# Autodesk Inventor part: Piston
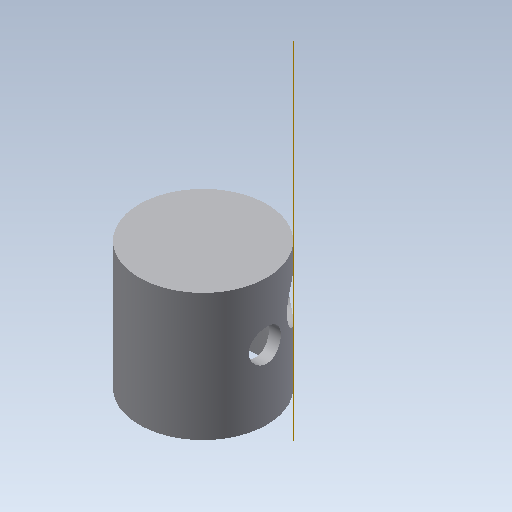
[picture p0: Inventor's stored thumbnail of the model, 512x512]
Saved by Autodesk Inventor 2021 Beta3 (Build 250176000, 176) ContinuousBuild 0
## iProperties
Created: 2012-08
Part Number: Piston
Material: Aluminum 6061
Document SubType Name: Modeling
Designer: John
Mass: 1.96844 g
Surface Area: 13.1985 cm^2
Volume: 0.72636 cm^3
Density: 2.71 g/cm^3
Appearance: Aluminum - Flat
Author: John
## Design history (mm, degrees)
sketch "Sketch1"
  geometry: C1 r 6.921 at (0, 0); 1 further point
  constraints: 1 centre point, 1 coincident
  dimensions: "d0" = 13.843 diameter of C1
extrude "Extrusion1" new body sketch "Sketch1" distance "d1" = 13.843; taper "d2" = 0 deg
hole "Hole2" diameter "d14" = 12.192; stored, may be unused: countersink angle "d18" = 82 deg, drill point angle "d20" = 0 deg; dims "d12" = 25.4, "d13" = 25.4, "d15" = 19.05, "d16" = 9.525, "d17" = 6.35, "d19" = 3.175
hole "Hole1" diameter "d5" = 11.43; stored, may be unused: countersink angle "d9" = 82 deg, drill point angle "d11" = 0 deg; dims "d6" = 19.05, "d7" = 9.525, "d8" = 6.35, "d10" = 9.144, "d28" = 25.4, "d29" = 25.4
sketch "Sketch2"
  geometry: L1 (13.843, -6.921)-(13.843, 6.921) reference; L2 (13.843, 0)-(7.493, 0); C1 r 1.74 at (7.493, 0); 1 further point
  constraints: 2 end point, 1 centre point, 1 coincident, 1 midpoint, 1 perpendicular
  dimensions: "d21" = 6.35 distance of L2.start L2.end; "d22" = 3.4798 diameter of C1
extrude "Extrusion2" cut sketch "Sketch2" extent not by distance; stored distance "d23" = 13.843; taper "d24" = 0 deg
sketch "Workplane Control Sketch"
  geometry: L1 (0, 0)-(4.894, 4.894); L2 (0, 0)-(0, 6.921); A1 r 6.921 centre (0, 0) between (4.894, 4.894) and (0, 6.921) reference
  constraints: 4 end point, 2 point on circle, 1 vertical
  dimensions: "d25" = 45 deg angle of L2 L1
workplane "Work Plane1"
sketch "Sketch4"
  geometry: L1 (0, 0)-(-5.08, 0); C1 r 2.54 at (-5.08, 0); 1 further point
  constraints: 2 end point, 1 centre point, 1 coincident, 1 horizontal
  dimensions: "d26" = 5.08 distance of L1.start L1.end; "d27" = 5.08 diameter of C1
extrude "Extrusion3" cut sketch "Sketch4" stored distance "d30" = 13.843; taper "d31" = 0 deg
body "Solid1"
node "Projected Loop1"
